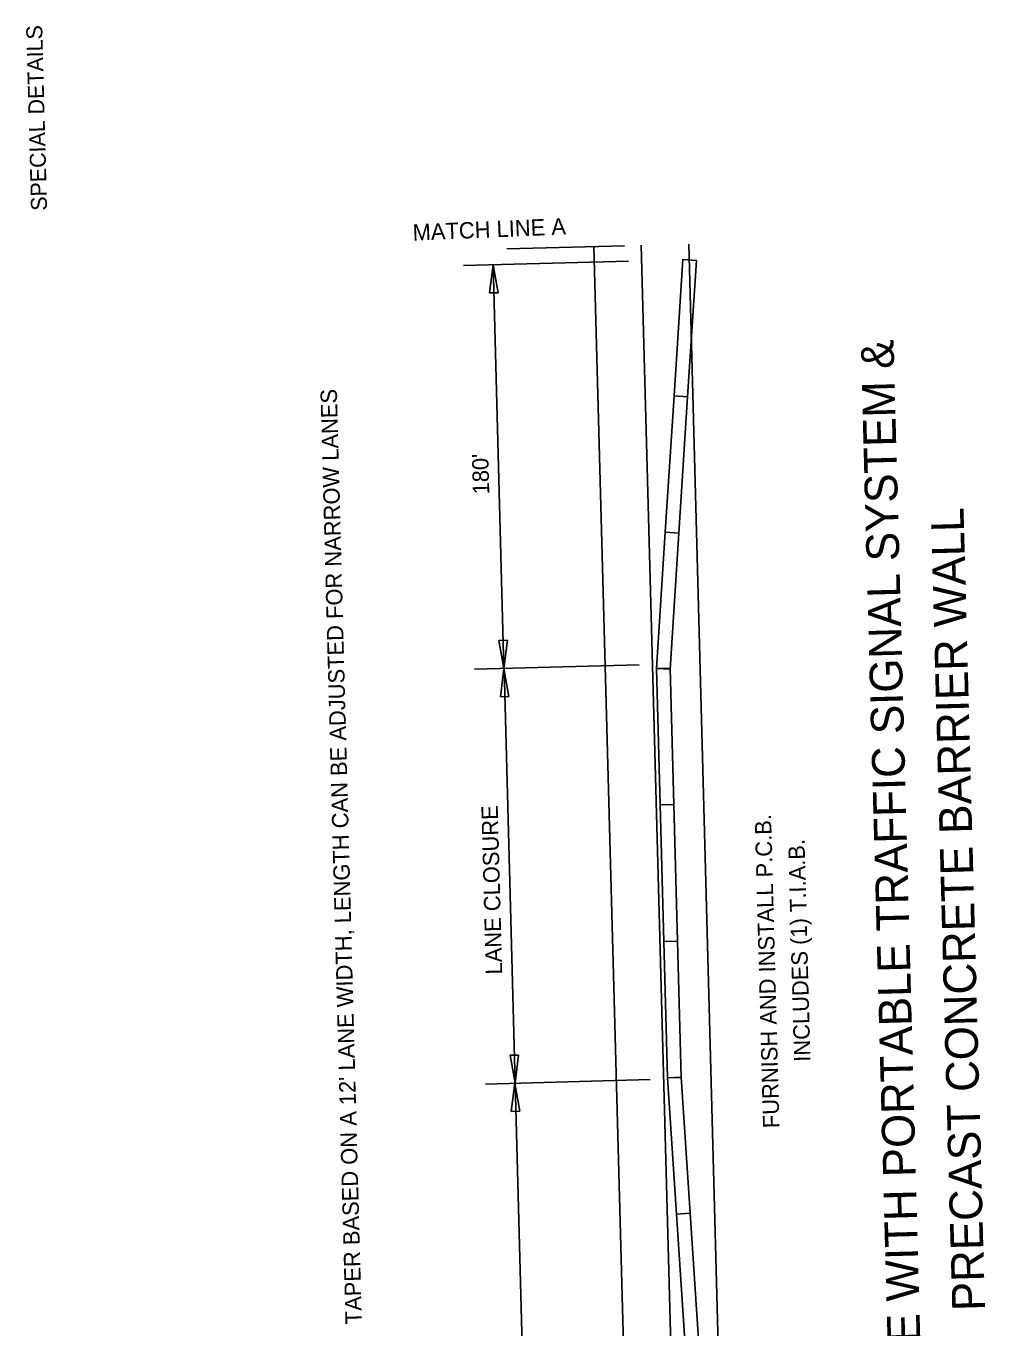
# Model space of a CAD drawing. Extents: x 1929624 to 1932070, y 596315 to 605533.
# Drawn here: x 1930711.6 to 1931062.8, y 597266 to 597742.7 of the extents above; entities that cross this region are included whole.
import ezdxf

# ---------------------------------------------------------------- set-up
doc = ezdxf.new("R2010")
doc.units = 0
for name, color, linetype in [('Default', 7, 'Continuous'), ('R_Border Prem', 7, 'Continuous'), ('R_No Plot', 7, 'Continuous'), ('T_Vehicle Path Rt', 7, 'Continuous')]:
    doc.layers.add(name, color=color, linetype=linetype)

msp = doc.modelspace()

# ---------------------------------------------------------------- linework, layer by layer
at = {"layer": 'Default'}
for p, q in [((1930887.73, 597661.11), (1930930.77, 597662.27)), ((1930937.4, 596998.85), (1930919.6, 597661.97)), ((1930954.78, 596999.31), (1930936.98, 597662.44)), ((1930972.16, 596999.78), (1930954.36, 597662.9)), ((1930871.91, 597655.05), (1930932.24, 597656.67)), ((1930881.42, 597645), (1930882.69, 597655.34)), ((1930886.66, 597507.5), (1930882.69, 597655.34)), ((1930882.69, 597655.34), (1930884.51, 597645.08)), ((1930884.51, 597645.08), (1930881.42, 597645)), ((1930884.84, 597517.76), (1930887.93, 597517.84)), ((1930886.66, 597507.5), (1930884.84, 597517.76)), ((1930887.93, 597517.84), (1930886.66, 597507.5)), ((1930875.88, 597507.21), (1930936.2, 597508.83)), ((1930885.39, 597497.16), (1930886.66, 597507.5)), ((1930886.66, 597507.5), (1930888.48, 597497.24)), ((1930886.79, 597507.51), (1930890.74, 597355.62)), ((1930888.48, 597497.24), (1930885.39, 597497.16)), ((1930888.91, 597365.88), (1930892.01, 597365.96)), ((1930892.01, 597365.96), (1930890.74, 597355.62)), ((1930890.74, 597355.62), (1930888.91, 597365.88)), ((1930879.95, 597355.33), (1930940.28, 597356.95)), ((1930889.33, 597345.27), (1930890.6, 597355.62)), ((1930890.6, 597355.62), (1930892.43, 597345.36)), ((1930890.74, 597355.62), (1930897.44, 597105.99)), ((1930892.43, 597345.36), (1930889.33, 597345.27))]:
    msp.add_line(p, q, dxfattribs=at)
at = {"layer": 'T_Vehicle Path Rt'}
for points in [[(1930948.96, 597607.31), (1930952.18, 597657.21), (1930957.17, 597656.88), (1930953.95, 597606.99)], [(1930945.73, 597557.42), (1930948.96, 597607.31), (1930953.95, 597606.99), (1930950.72, 597557.09)], [(1930942.51, 597507.52), (1930945.73, 597557.42), (1930950.72, 597557.09), (1930947.5, 597507.2)], [(1930943.85, 597457.54), (1930942.51, 597507.52), (1930947.51, 597507.65), (1930948.85, 597457.67)], [(1930945.19, 597407.56), (1930943.85, 597457.54), (1930948.85, 597457.67), (1930950.19, 597407.69)], [(1930946.53, 597357.57), (1930945.19, 597407.56), (1930950.19, 597407.69), (1930951.53, 597357.71)], [(1930949.85, 597307.68), (1930946.53, 597357.57), (1930951.52, 597357.91), (1930954.84, 597308.02)], [(1930953.16, 597257.79), (1930949.85, 597307.68), (1930954.84, 597308.02), (1930958.15, 597258.13)]]:
    msp.add_lwpolyline(points, close=True, dxfattribs=at)

# ---------------------------------------------------------------- texts
at = {"layer": 'Default'}
for s, height, rotation, p in [('MATCH LINE A', 6, 2.3436, (1930853.35, 597664.12)), ('LANE CLOSURE WITH PORTABLE TRAFFIC SIGNAL SYSTEM &', 12, 91.5377, (1931042.21, 597147.6)), ("180'", 6, 91.5377, (1930881.33, 597571.29)), ('PRECAST CONCRETE BARRIER WALL', 12, 91.5377, (1931062.87, 597272.4)), ('LANE CLOSURE', 6, 91.5377, (1930886.05, 597395.52)), ('FURNISH AND INSTALL P.C.B. ', 6, 91.5377, (1930987.58, 597339.26)), ('INCLUDES (1) T.I.A.B.', 6, 91.5377, (1930998.93, 597363.57))]:
    msp.add_text(s, height=height, rotation=rotation, dxfattribs=at).set_placement(p)
at = {"layer": 'R_Border Prem'}
msp.add_text('SPECIAL DETAILS', height=5.862, rotation=91.5377, dxfattribs=at).set_placement((1930719.38, 597675.16))
at = {"layer": 'R_No Plot'}
msp.add_text("TAPER BASED ON A 12' LANE WIDTH, LENGTH CAN BE ADJUSTED FOR NARROW LANES", height=6, rotation=91.5377, dxfattribs=at).set_placement((1930834.65, 597267.46))

doc.saveas('drawing.dxf')
